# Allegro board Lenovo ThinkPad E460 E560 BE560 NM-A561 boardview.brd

Outline 251.2 x 195.15 mm; copper layers: TOP, GND1, IN1, IN2, VCC, IN3, GND2, BOTTOM. Coordinates in mm from the lower left corner of the outline.

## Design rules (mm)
net group 2: nets USB3P2_TXN_C USB3P2_TXP_C
net group AC: nets ACN ACP
net group CLKOUT_ITPXDP_: nets CLKOUT_ITPXDP_N CLKOUT_ITPXDP_P
net group CPU_EDP_AUX: nets CPU_EDP_AUX CPU_EDP_AUX#
net group CPU_EDP_TX0: nets CPU_EDP_TX0+ CPU_EDP_TX0-
net group CPU_EDP_TX1: nets CPU_EDP_TX1+ CPU_EDP_TX1-
net group CS1: nets CSN1 CSP1
net group DDI1_MUX_TX0: nets DDI1_MUX_TX0+_R DDI1_MUX_TX0-_R
net group DDI1_MUX_TX1: nets DDI1_MUX_TX1+_R DDI1_MUX_TX1-_R
net group DDI1_MUX_TX2: nets DDI1_MUX_TX2+_R DDI1_MUX_TX2-_R
net group DDI1_MUX_TX3: nets DDI1_MUX_TX3+_R DDI1_MUX_TX3-_R
net group DDRA_CTL: nets DDRA_CS0_DIMMA# DDRA_CS1_DIMMA#
net group DIFFPAIR0: nets CLK_PCIE_VGA CLK_PCIE_VGA#
net group DIFFPAIR15: nets USB20_N4_FFC_CON USB20_P4_FFC_CON
net group DIFFPAIR16: nets USB3P3_TXN_COAX_CON USB3P3_TXP_COAX_CON
net group DIFFPAIR23: nets USB3P2_TXN_CON USB3P2_TXP_CON
net group DIFFPAIR24: nets USB3P2_RXN_CON USB3P2_RXP_CON
net group DIFFPAIR30: nets USB3P4_RXN_COAX_CON USB3P4_RXP_COAX_CON
net group DIFFPAIR34: nets PCIE_CRX_C_GTX_N3 PCIE_CRX_C_GTX_P3
net group DIFFPAIR35: nets PCIE_CRX_C_GTX_N2 PCIE_CRX_C_GTX_P2
net group DIFFPAIR36: nets PCIE6_CRX_DTX_N PCIE6_CRX_DTX_P
net group DIFFPAIR37: nets USB3P5_TXN USB3P5_TXP
net group DIFFPAIR38: nets USB3P5_RXN USB3P5_RXP
net group DIFFPAIR39: nets USB3P5_RXN_CON USB3P5_RXP_CON
net group DIFFPAIR40: nets USB3P5_TXN_CON USB3P5_TXP_CON
net group DIFFPAIR41: nets USB3P5_TXN_C USB3P5_TXP_C
net group DIFFPAIR42: nets CPU_EDP_TX0+_CON CPU_EDP_TX0-_CON
net group DIFFPAIR43: nets CPU_EDP_TX1+_CON CPU_EDP_TX1-_CON
net group DIFFPAIR44: nets CPU_EDP_AUX#_CON CPU_EDP_AUX_CON
net group DIFFPAIR45: nets HDMI_TXC+_CON HDMI_TXC-_CON
net group DIFFPAIR46: nets DDI1_MUX_TX3+ DDI1_MUX_TX3-
net group DIFFPAIR47: nets DDI1_MUX_TX2+ DDI1_MUX_TX2-
net group DIFFPAIR48: nets DDI1_MUX_TX1+ DDI1_MUX_TX1-
net group DIFFPAIR49: nets DDI1_MUX_TX0+ DDI1_MUX_TX0-
net group DIFFPAIR50: nets PCH_MUX_AUX PCH_MUX_AUX#
net group DIFFPAIR51: nets USB20_N1_CON USB20_P1_CON
net group DIFFPAIR52: nets USB3P1_TXN_CON USB3P1_TXP_CON
net group DIFFPAIR53: nets USB3P1_TXN_C USB3P1_TXP_C
net group DIFFPAIR54: nets USB3P1_RXN_CON USB3P1_RXP_CON
net group DIFFPAIR55: nets PCIE4_CRX_DTX_N_C PCIE4_CRX_DTX_P_C
net group DIFFPAIR56: nets PCIE3_CTX_C_DRX_N PCIE3_CTX_C_DRX_P
net group DIFFPAIR58: nets USB20_N3_FFC_CON USB20_P3_FFC_CON
net group DIFFPAIR60: nets SATA_PTX_C_DRX_N0 SATA_PTX_C_DRX_P0
net group DIFFPAIR61: nets SATA_PRX_C_DTX_N0 SATA_PRX_C_DTX_P0
net group DIFFPAIR62: nets SATA_PTX_C_DRX_N1 SATA_PTX_C_DRX_P1
net group DOCK_TX0: nets DOCK_TX0+ DOCK_TX0-
net group DP: nets DOCK_AUX DOCK_AUX#
net group DP_H_HDMI_TX0: nets H_HDMI_TX0+ H_HDMI_TX0-
net group DP_H_HDMI_TX1: nets H_HDMI_TX1+ H_HDMI_TX1-
net group DP_H_HDMI_TX2: nets H_HDMI_TX2+ H_HDMI_TX2-
net group DP_N56767499: nets N56767499 N56767500
net group DP_PCIE6_CRX_DTX: nets PCIE6_CRX_C_DTX_N PCIE6_CRX_C_DTX_P
net group DP_PCIE6_CTX_DRX: nets PCIE6_CTX_DRX_N PCIE6_CTX_DRX_P
net group DP_PCIE_CRX_C_GTX_N0: nets PCIE_CRX_C_GTX_N0 PCIE_CRX_C_GTX_P0
net group DP_PCIE_CRX_C_GTX_N1: nets PCIE_CRX_C_GTX_N1 PCIE_CRX_C_GTX_P1
net group DP_PCIE_CRX_C_GTX_N3: nets PCIE_CRX_GTX_N3 PCIE_CRX_GTX_P3
net group DP_SATA_PRX_C_DTX_N1: nets SATA_PRX_C_DTX_N1 SATA_PRX_C_DTX_P1
net group FBA_CLK: nets FBB_WCKB0_1 FBB_WCKB0B_1
net group HDMI_TX0: nets HDMI_TX0+_CON HDMI_TX0-_CON
net group HDMI_TX1: nets HDMI_TX1+_CON HDMI_TX1-_CON
net group HDMI_TX2: nets HDMI_TX2+_CON HDMI_TX2-_CON
net group HDMI_TXC_CON: nets H_HDMI_TXC+ H_HDMI_TXC-
net group HGND: nets EXT_MIC_A EXT_MIC_B
net group MINIDP_TX1: nets DOCK_TX1+ DOCK_TX1-
net group PCH_MUX_AUX: nets PCH_MUX_AUX#_C PCH_MUX_AUX_C
net group PCIE3_CTX_C_DRX_: nets PCIE3_CTX_DRX_N PCIE3_CTX_DRX_P
net group PCIE4_CRX_DTX_: nets PCIE4_CRX_DTX_N PCIE4_CRX_DTX_P
net group PCIE4_CTX_C_DRX_: nets PCIE4_CTX_DRX_N PCIE4_CTX_DRX_P
net group PCIE6_CTX_DRX: nets PCIE6_CTX_C_DRX_N PCIE6_CTX_C_DRX_P
net group PCIE_CRX_C_GTX: nets PCIE_CRX_GTX_N1 PCIE_CRX_GTX_P1
net group PCIE_CRX_C_GTX_: nets PCIE_CRX_GTX_N0 PCIE_CRX_GTX_P0
net group PCIE_CRX_C_GTX_2: nets PCIE_CRX_GTX_N2 PCIE_CRX_GTX_P2
net group PCIE_WLAN_S20(15)/20(15): nets PCIE3_CRX_DTX_N PCIE3_CRX_DTX_P
net group PECI_18/18: nets H_PECI PECI
net group RTC_R: nets PCH_RTCRST# PCH_SRTCRST#
net group RTCX: nets PCH_RTCX1 PCH_RTCX2
net group SATA_PRX_C_DTX_P0: nets SATA_PRX_DTX_N0 SATA_PRX_DTX_P0
net group SATA_PRX_DTX_N1: nets SATA_PRX_DTX_N1 SATA_PRX_DTX_P1
net group SATA_PTX_C_DRX_N1: nets SATA_PTX_DRX_N1 SATA_PTX_DRX_P1
net group SATA_PTX_C_DRX_P0: nets SATA_PTX_DRX_N0 SATA_PTX_DRX_P0
net group SD_CLK_MS_DATA0: nets SD_CLK_MS_DATA0 SD_CLK_MS_DATA0_R
net group SD_CMD_MS_DATA2: nets SD_CMD_MS_DATA2 SD_CMD_MS_DATA2_R
net group SD_DATA0_MS_DATA1: nets SD_DATA0_MS_DATA1 SD_DATA0_MS_DATA1_R
net group SD_DATA2_MS_CLK: nets SD_DATA2_MS_CLK SD_DATA2_MS_CLK_R
net group SD_MS_DATA3: nets SD_MS_DATA3 SD_MS_DATA3_R
net group USB3P1: nets USB3P1_TXN USB3P1_TXP
net group USB3P1_RX: nets USB3P1_RXN USB3P1_RXP
net group USB3P2_RX: nets USB3P2_RXN USB3P2_RXP
net group USB20_P0: nets USB20_N1 USB20_P1
net group USB20_P1: nets USB20_N2_CON USB20_P2_CON
net group USB201: nets USB20N2 USB20P2
net group VSUM: nets VSUM+ VSUM-
net group 1: nets PCIE4_CTX_C_DRX_P
net group AUDIO_HP_S10: nets +MICBIASB HP_OUTL HP_OUTL_CON HP_OUTR HP_OUTR_CON N61210291
net group CPU SIDEBAND_S12(13.5): nets DDR3_DRAMRST# H_CPUPWRGD H_PROCHOT_EC H_THERMTRIP# THRMTRIP# VR_HOT#_R
net group DDI: nets AUXN AUXP DDI2_VGA_TX0+ DDI2_VGA_TX0- DDI2_VGA_TX1+ DDI2_VGA_TX1- ML0N ML0P ML1N ML1P PCH_VGA_AUX PCH_VGA_AUX#
net group DDR-DQS: nets DDR_A_DQS0 DDR_A_DQS3 DDR_A_DQS4 DDR_A_DQS5 DDR_A_DQS6 DDR_A_DQS7 DDR_A_DQS#0 DDR_A_DQS#3 DDR_A_DQS#4 DDR_A_DQS#5 DDR_A_DQS#6 DDR_A_DQS#7 DDR_B_DQS0 DDR_B_DQS1 DDR_B_DQS2 DDR_B_DQS3 DDR_B_DQS4 DDR_B_DQS5 DDR_B_DQS6 DDR_B_DQS7 DDR_B_DQS#0 DDR_B_DQS#1 DDR_B_DQS#2 DDR_B_DQS#3 DDR_B_DQS#4 DDR_B_DQS#5 DDR_B_DQS#6 DDR_B_DQS#7
net group DDRB_CTL: nets DDRB_CS0_DIMMB#
net group EDPCOMP_S25/25: nets EDP_COMP
net group FBB_CMD/CTL: nets FBA_RST#
net group HDA_S5/5: nets HDA_RST# HDA_SYNC PCH_HDA_RST# PCH_HDA_SDIN0 PCH_HDA_SDIN0_R PCH_HDA_SDOUT PCH_HDA_SYNC
net group LAN_S20/20: nets MDI_0+ MDI_0- MDI_1+ MDI_1- MDI_2+ MDI_2- MDI_3+ MDI_3- RJ45_TXD0N RJ45_TXD0P RJ45_TXD1N RJ45_TXD1P RJ45_TXD2N RJ45_TXD2P RJ45_TXD3N RJ45_TXD3P
net group LVDS: nets +LEDVDD
net group PCIE_CLK_S20(15)/20(15): nets CLK_PCIE_CR CLK_PCIE_CR# CLK_PCIE_LAN CLK_PCIE_LAN# CLK_PCIE_WLAN CLK_PCIE_WLAN#
net group PCIE_GPU: nets PCIE3_PTX_DRX_N2 PCIE3_PTX_DRX_P2 PCIE4_PTX_DRX_N3 PCIE4_PTX_DRX_P3 PCIE_CTX_C_GRX_N2 PCIE_CTX_C_GRX_N3 PCIE_CTX_C_GRX_P2 PCIE_CTX_C_GRX_P3
net group PCIE_LAN: nets PCIE1_PTX_DRX_N0 PCIE1_PTX_DRX_P0 PCIE2_PTX_DRX_N1 PCIE2_PTX_DRX_P1 PCIE4_CTX_C_DRX_N PCIE_CTX_C_GRX_N0 PCIE_CTX_C_GRX_N1 PCIE_CTX_C_GRX_P0 PCIE_CTX_C_GRX_P1
net group PWR: nets +1.65V_LDO +3V_LDO +3VALW_LAN APDIN P3 SPI_IO2 SPI_IO3 VSYSTEM
net group SMBUS_S7/7: nets EC_SMB_CK1 EC_SMB_DA1 PCH_SMB_CLK PCH_SMB_DATA PCH_SML0_CLK PCH_SML0_DAT PCH_SML1CLK PCH_SML1DATA PM_SMB_CLK PM_SMB_DAT
net group SPI: nets FSCE# LAN_WAKE# LAN_WAKE#_R PCH_SLP_LAN# PCH_SLP_WLAN# SPI_CS0#_8MB SPI_FMISO SPI_FMOSI# SPI_SI_8MB SPI_SO_8MB
net group SPI5/5: nets SPI_CS1#_4MB SPI_FSCK SPI_IO2_4MB SPI_IO2_8MB SPI_IO3_4MB SPI_IO3_8MB SPI_SI SPI_SI_4MB SPI_SO SPI_SO_4MB
net group SPI_CLK: nets CLK_PCI_EC DMIC_CLK HDA_BCLK N43769362 PCH_HDA_BCLK PCH_PCI_CLK_R SPI_CLK SPI_CLK_4MB SPI_CLK_8MB SPI_CLK_R
net group SVID_S18/18: nets VR_SVID_ALRT# VR_SVID_CLK VR_SVID_DAT
net group USB20: nets USB20_N2 USB20_N3 USB20_N4 USB20_N5 USB20_N5_CON USB20_N9 USB20_P2 USB20_P3 USB20_P4 USB20_P5 USB20_P5_CON USB20_P9
net group USB20_S20(15)/20(15): nets USB20_N6 USB20_N7 USB20_N7_CMOS USB20_P6 USB20_P7 USB20_P7_CMOS
net group USB30: nets USB3P2_TXN USB3P2_TXP USB3P3_RXN USB3P3_RXN_COAX_CON USB3P3_RXP USB3P3_RXP_COAX_CON USB3P3_TXN USB3P3_TXP USB3P4_RXN USB3P4_RXP USB3P4_TXN USB3P4_TXN_COAX_CON USB3P4_TXP USB3P4_TXP_COAX_CON
net group VGA: nets VGA_BLUE VGA_GREEN VGA_RED
net group WLAN_CTRL_S10/10: nets CL_CLK_WLAN CL_DATA_WLAN CL_RST_WLAN#
nets with their own width: min track width 0.254; nets +3VALW

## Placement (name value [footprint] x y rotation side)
AOU1  -  [TPS2546RTER_QFN16_4X4]  35.95 17.85 90 top
C1  0.1U_0402_10V6-K  [C_0402]  119.44 179.29 270 bottom
C2  2200P_0402_50V7-K  [C_0402]  118.17 177.76 180 bottom
C3  2200P_0402_50V7-K  [C_0402]  116.41 177.76 180 bottom
C4  100P_0402_50V8-J  [C_0402]  34.75 105.04 90 bottom
C5  100P_0402_50V8-J  [C_0402]  50.48 41.67 0 bottom
C8  1U_0402_6.3VA-K  [C_0402]  86.86 134.45 315 bottom
C9  4.7U_0603_6.3V6-K  [C_0603]  92.55 135.85 135 bottom
C10  1U_0402_6.3VA-K  [C_0402]  94.92 143.81 225 bottom
C11  4.7U_0603_6.3V6-K  [C_0603]  93.57 138.73 225 bottom
C12  4.7U_0805_25V6-K  [C_0805]  100.52 134.45 315 top
C13  0.1U_0402_10V7-K  [C_0402]  94.87 127.5 135 top
C14  0.1U_0402_10V7-K  [C_0402]  94.23 126.87 135 top
C15  0.1U_0402_10V7-K  [C_0402]  93.6 126.23 135 top
C16  0.1U_0402_10V7-K  [C_0402]  92.96 125.6 135 top
C17  0.1U_0402_10V7-K  [C_0402]  96.14 128.77 135 top
C18  0.1U_0402_10V7-K  [C_0402]  95.5 128.14 135 top
C19  10U_0805_10V6-K  [C_0805]  196.91 128.47 90 bottom
C20  10U_0805_10V6-K  [C_0805]  198.68 128.47 90 bottom
C21  1U_0402_10V6-K  [C_0402]  195.51 128.56 90 bottom
C22  0.1U_0402_25V6-K  [C_0402]  193.73 128.56 90 bottom
C23  1000P_0402_50V7-K  [C_0402]  194.62 128.56 90 bottom
C24  .01U_0402_16V7-K  [C_0402]  172.9 128.89 270 bottom
C25  .01U_0402_16V7-K  [C_0402]  173.79 128.89 270 bottom
C26  .01U_0402_16V7-K  [C_0402]  176.71 128.89 270 bottom
C27  .01U_0402_16V7-K  [C_0402]  177.6 128.89 270 bottom
C28  0.1U_0402_10V7-K  [C_0402]  87.86 121.72 90 top
C29  0.1U_0402_10V7-K  [C_0402]  86.96 121.72 90 top
C44  100P_0402_50V8J  [C_0402]  31.8 100.42 180 top
C45  100P_0402_50V8J  [C_0402]  31.8 101.31 180 top
C50  0.1U_0402_10V6-K  [C_0402]  120.94 123.94 0 bottom
C51  10U_0603_6.3V6-M  [C_0603]  120.92 122.87 0 bottom
C52  0.1U_0402_10V6-K  [C_0402]  215.91 93.64 180 top
C69  1U_0402_6.3VA-K  [C_0402]  183.65 25.82 180 top
C70  0.1U_0402_10V7-K  [C_0402]  191.37 28.26 270 top
C71  1000P_0402_25V7-K  [C_0402]  188.96 25.03 0 top
C72  100P_0402_50V8-J  [C_0402]  188.96 24.14 0 top
C73  1U_0402_6.3VA-K  [C_0402]  183.24 23.36 180 top
C74  0.1U_0402_10V7-K  [C_0402]  190 22.26 90 top
C75  .01U_0402_16V7-K  [C_0402]  214.79 37.15 90 top
C115  0.1U_0402_10V6-K  [C_0402]  235.82 144.34 180 top
C116  0.1U_0402_10V6-K  [C_0402]  235.82 143.45 180 top
C119  0.1U_0402_10V6-K  [C_0402]  30.33 23.48 270 top
C121  0.1U_0402_10V7-K  [C_0402]  24.01 44.11 180 top
C122  150U_B2_6.3VM_R35M  [C_B2]  19.97 48.58 270 bottom
C123  470P_0402_50V7-K  [C_0402]  17.53 49.26 90 bottom
C124  0.1U_0402_10V7-K  [C_0402]  24.01 43.22 180 top
C129  .01U_0402_16V7-K  [C_0402]  222.87 42.84 0 bottom
C130  .01U_0402_16V7-K  [C_0402]  222.87 43.73 0 bottom
C131  4.7U_0603_6.3V6-K  [C_0603]  223.96 46.46 270 bottom
C132  1U_0402_6.3VA-K  [C_0402]  222 50.84 180 bottom
C164  .01U_0402_16V7-K  [C_0402]  222.87 40.93 0 bottom
C165  .01U_0402_16V7-K  [C_0402]  222.87 41.82 0 bottom
C171  .01U_0402_16V7-K  [C_0402]  242.58 182.28 180 top
C172  1U_0402_6.3VA-K  [C_0402]  243.92 182.28 90 top
C202  2200P_0402_50V7-K  [C_0402]  192.84 128.56 90 bottom
C203  47P_0402_50V8-J  [C_0402]  191.95 128.56 90 bottom
C204  2200P_0402_50V7-K  [C_0402]  185.65 123.36 0 top
C205  47P_0402_50V8-J  [C_0402]  185.68 124.35 0 top
C747  2200P_0402_25V7-K  [C_0402]  130.44 64.17 180 top
C749  10U_0402_6.3V  [C_0402]  127.31 68.9 270 top
C750  1U_0402_6.3V6-K  [C_0402]  185.35 14.47 270 top
C751  4.7U_0603_10V6-K  [C_0603]  189.86 15.53 0 top
C8496  0.1U_0402_10V6-K  [C_0402]  114.13 116.04 270 bottom
C8497  0.1U_0402_10V6-K  [C_0402]  115.02 116.04 270 bottom
C8498  0.1U_0402_10V6-K  [C_0402]  123.6 126.89 270 bottom
C8499  10U_0603_6.3V6-M  [C_0603]  112.54 123.1 180 bottom
C8528  470P_0402_50V7-K  [C_0402]  33.92 9.9 0 top
C8529  0.1U_0402_10V7-K  [C_0402]  26.47 16.93 180 top
C8530  0.1U_0402_10V7-K  [C_0402]  26.47 15.97 180 top
C8531  150U_B2_6.3VM_R35M  [C_B2]  33.45 12.05 180 top
C8532  0.1U_0402_10V7-K  [C_0402]  39.1 17.31 0 top
C8533  2200P_0402_50V7-K  [C_0402]  101.66 139.99 225 top
C8534  2200P_0402_50V7-K  [C_0402]  94.04 135.85 315 bottom
C8536  4.7U_0603_6.3V6-K  [C_0603]  63.61 57.49 180 top
C8537  0.1U_0402_10V7-K  [C_0402]  63.4 58.69 180 top
C8540  0.22U_0402_10V6-K  [C_0402]  69.53 53.96 270 top
C8541  0.1U_0402_6.3V7-K  [C_0402]  130.54 67.98 90 top
C8542  0.1U_0402_10V6-K  [C_0402]  102.41 82.91 0 top
C8543  10U_0402_6.3V6-M  [C_0402]  126.88 63.86 180 top
C8544  0.1U_0402_10V7-K  [C_0402]  124.33 65.11 90 top
C8545  0.1U_0402_10V6-K  [C_0402]  23.17 23.99 270 top
CA1  0.1U_0402_10V7-K  [C_0402]  195.15 26.38 270 top
CA2  4.7U_0603_10V6-K  [C_0603]  196.97 21.5 0 top
CA3  4.7U_0603_10V6-K  [C_0603]  196.97 20.28 0 top
CA4  0.1U_0402_10V7-K  [C_0402]  203.46 20.28 180 top
CA5  0.1U_0402_10V7-K  [C_0402]  203.89 23.74 180 top
CA6  0.1U_0402_10V7-K  [C_0402]  214.08 27.6 270 top
CA7  4.7U_0603_10V6-K  [C_0603]  212.99 26.11 90 top
CA8  0.1U_0402_10V7-K  [C_0402]  213.62 16.55 0 top
CA9  1U_0402_6.3VA-K  [C_0402]  213.62 15.64 0 top
CA10  0.1U_0402_10V7-K  [C_0402]  210.67 15.1 270 top
CA11  2.2U_0402_6.3V6-M  [C_0402]  211.74 15.04 270 top
CA12  0.1U_0402_10V7-K  [C_0402]  195.18 27.22 90 top
CA13  1U_0402_6.3VA-K  [C_0402]  208.49 14.92 270 top
CA14  1U_0402_6.3VA-K  [C_0402]  203.82 18.05 180 top
CA15  1U_0402_6.3VA-K  [C_0402]  213.39 13.86 270 top
CA16  0.1U_0402_10V7-K  [C_0402]  203.05 25.95 0 top
CA17  1U_0402_6.3V6-K  [C_0402]  205.11 17.16 180 top
CA18  2.2U_0402_6.3V6-M  [C_0402]  205.81 16.07 180 top
CA19  0.1U_0402_10V7-K  [C_0402]  209.38 13.98 90 top
CA22  0.1U_0402_10V7-K  [C_0402]  198.35 29.12 0 top
CA23  0.1U_0402_10V7-K  [C_0402]  201.94 27.29 90 top
CA24  0.1U_0402_10V7-K  [C_0402]  201.99 29.1 0 top
CA25  470P_0402_50V7-K  [C_0402]  201.05 23.53 180 top
CA26  470P_0402_50V7-K  [C_0402]  201.05 25.82 180 top
CA27  470P_0402_50V7-K  [C_0402]  201.05 19.98 180 top
CA28  470P_0402_50V7-K  [C_0402]  201.05 17.69 180 top
CA29  2.2U_0402_6.3V6-K  [C_0402]  215.6 17.54 0 top
CA30  2.2U_0402_6.3V6-K  [C_0402]  215.6 18.43 0 top
CA31  10U_0603_6.3V6-M  [C_0603]  215.66 19.47 0 top
CA32  10U_0603_6.3V6-M  [C_0603]  215.69 20.66 0 top
CA40  150P_0402_50V8-J  [C_0402]  215.98 24.96 270 top
CA42  4.7U_0603_10V6-K  [C_0603]  208.79 26.09 90 top
CA43  47P_0402_50V8-J  [C_0402]  215.88 26.68 90 top
CC1  1U_0402_10V6K  [C_0402]  118.4 72.76 180 top
CC2  1U_0402_10V6-K  [C_0402]  102.41 81.13 0 top
CC3  3.9P_0402_50V8-B  [C_0402]  116.31 88.89 90 top
CC4  3.9P_0402_50V8-B  [C_0402]  116.31 88.03 270 top
CC5  1U_0402_10V6K  [C_0402]  115.7 72.73 0 top
CC6  12P_0402_50V8-J  [C_0402]  90.53 118.21 0 bottom
CC7  12P_0402_50V8-J  [C_0402]  89.67 118.21 180 bottom
CC9  100P_0402_25V8J  [C_0402]  45.95 108.14 180 top
CC18  0.1U_0402_10V7-K  [C_0402]  100.41 110.71 270 bottom
CC19  0.1U_0402_10V7-K  [C_0402]  101.3 110.71 270 bottom
CC20  0.1U_0402_10V7-K  [C_0402]  101.15 118.48 270 bottom
CC21  0.1U_0402_10V7-K  [C_0402]  100.26 118.48 270 bottom
CC22  0.1U_0402_10V6-K  [C_0402]  79.38 132.25 180 bottom
CC23  0.1U_0402_10V7-K  [C_0402]  94.54 118.48 270 bottom
CC24  0.1U_0402_10V7-K  [C_0402]  94.42 115.48 270 bottom
CC25  0.1U_0402_10V7-K  [C_0402]  138.13 124.98 270 bottom
CC26  0.1U_0402_10V7-K  [C_0402]  227.74 15.46 180 top
CC46  1U_0402_10V6K  [C_0402]  126.87 97.46 270 bottom
CC47  1U_0402_10V6K  [C_0402]  98 93.18 180 top
CC49  1U_0402_10V6K  [C_0402]  100.01 99.81 0 top
CC50  1U_0402_10V6K  [C_0402]  102.14 96.41 180 top
CC52  1U_0402_10V6K  [C_0402]  99.35 96.69 180 top
CC58  1U_0402_10V6K  [C_0402]  100.96 84.38 270 top
CC59  1U_0402_10V6K  [C_0402]  102.41 82.02 0 top
CC60  1U_0402_10V6K  [C_0402]  120.12 88.24 0 top
CC61  1U_0402_10V6K  [C_0402]  125.02 88.89 0 top
CC68  1U_0402_10V6K  [C_0402]  97.8 104.74 180 top
CC69  1U_0402_10V6K  [C_0402]  97.67 107.61 180 top
CC70  1U_0402_10V6K  [C_0402]  95.26 104.71 90 top
CC86  0.1U_0402_10V7-K  [C_0402]  96.32 118.48 270 bottom
CC87  0.1U_0402_10V7-K  [C_0402]  97.21 118.48 270 bottom
CC88  0.1U_0402_10V7-K  [C_0402]  99.24 118.48 270 bottom
CC89  0.1U_0402_10V7-K  [C_0402]  98.23 118.48 270 bottom
CC90  0.1U_0402_10V7-K  [C_0402]  95.43 118.48 270 bottom
CC91  0.1U_0402_10V7-K  [C_0402]  95.31 115.48 270 bottom
CC92  0.1U_0402_10V7-K  [C_0402]  102.16 118.48 270 bottom
CC93  0.1U_0402_10V7-K  [C_0402]  103.05 118.48 270 bottom
CC94  1U_0402_10V6K  [C_0402]  85.53 84.83 270 top
CC95  1U_0402_10V6K  [C_0402]  98.61 94.07 0 top
CC96  1U_0402_10V6K  [C_0402]  101.97 91.56 270 top
CC97  1U_0402_10V6K  [C_0402]  115.63 94.68 0 top
CC99  1U_0402_10V6K  [C_0402]  98.18 72.05 180 top
CC102  100P_0402_25V8J  [C_0402]  45.95 109.03 180 top
CC104  10U_0603_6.3V6-M  [C_0603]  85.11 89.1 180 top
CC105  10U_0603_6.3V6-M  [C_0603]  93.26 89.24 180 top
CC106  1U_0201_6.3V6-M  [C_0201]  87.01 87.67 0 top
CC107  1U_0201_6.3V6-M  [C_0201]  86.29 88.94 0 top
CC108  1U_0201_6.3V6-M  [C_0201]  86.72 89.68 90 top
CC109  1U_0201_6.3V6-M  [C_0201]  86.09 89.68 90 top
CC123  10U_0603_6.3V6-M  [C_0603]  81.81 94.48 180 top
CC129  10U_0603_6.3V6-M  [C_0603]  76.17 90.67 180 top
CC130  10U_0603_6.3V6-M  [C_0603]  76.17 91.96 180 top
CC131  10U_0603_6.3V6-M  [C_0603]  77.54 91.91 0 top
CC133  10U_0603_6.3V6-M  [C_0603]  71.1 93.04 270 top
CC136  10U_0603_6.3V6-M  [C_0603]  88.26 114.59 90 bottom
CC137  10U_0603_6.3V6-M  [C_0603]  89.53 89.24 0 top
CC138  10U_0603_6.3V6-M  [C_0603]  95.05 117.07 90 top
CC139  10U_0603_6.3V6-M  [C_0603]  84.88 100.37 180 top
CC140  10U_0603_6.3V6-M  [C_0603]  86.99 115.17 90 top
CC141  10U_0603_6.3V6-M  [C_0603]  86.99 114.59 90 bottom
CC142  1U_0201_6.3V6-M  [C_0201]  88.28 91.61 0 top
CC143  1U_0201_6.3V6-M  [C_0201]  84.89 91.56 0 top
CC144  1U_0201_6.3V6-M  [C_0201]  116.26 111.63 90 top
CC145  1U_0201_6.3V6-M  [C_0201]  83.69 91.1 180 top
CC146  1U_0201_6.3V6-M  [C_0201]  78.2 95.57 0 top
CC147  1U_0201_6.3V6-M  [C_0201]  78.02 91.02 0 top
CC148  1U_0201_6.3V6-M  [C_0201]  72.3 97.84 270 top
CC149  1U_0201_6.3V6-M  [C_0201]  73.92 96.92 90 top
CC150  1U_0201_6.3V6-M  [C_0201]  78.17 98.57 0 top
CC151  1U_0201_6.3V6-M  [C_0201]  78.15 96.18 0 top
CC152  1U_0201_6.3V6-M  [C_0201]  54.79 92.71 90 top
CC153  1U_0201_6.3V6-M  [C_0201]  72.61 94.5 270 top
CC154  1U_0201_6.3V6-M  [C_0201]  53.78 96.09 270 top
CC155  1U_0201_6.3V6-M  [C_0201]  73.36 92.76 270 top
CC156  1U_0201_6.3V6-M  [C_0201]  53.78 98.81 90 top
CC157  1U_0201_6.3V6-M  [C_0201]  72.63 95.88 270 top
CC158  1U_0201_6.3V6-M  [C_0201]  72 94.5 270 top
CC159  1U_0201_6.3V6-M  [C_0201]  73.84 94.4 270 top
CC160  1U_0201_6.3V6-M  [C_0201]  78.17 97.96 0 top
CC161  1U_0201_6.3V6-M  [C_0201]  78.02 90.44 0 top
CC170  1U_0201_6.3V6-M  [C_0201]  81.36 91.07 180 top
CC171  1U_0201_6.3V6-M  [C_0201]  82.18 89.79 270 top
CC172  1U_0201_6.3V6-M  [C_0201]  90.6 91.61 180 top
CC173  1U_0201_6.3V6-M  [C_0201]  87 105.18 270 top
CC174  1U_0201_6.3V6-M  [C_0201]  87.95 100.62 180 top
CC175  1U_0201_6.3V6-M  [C_0201]  87.17 91.49 180 top
CC176  1U_0201_6.3V6-M  [C_0201]  84.89 91 0 top
CC177  1U_0201_6.3V6-M  [C_0201]  90.6 92.24 180 top
CC178  1U_0201_6.3V6-M  [C_0201]  88.28 92.88 0 top
CC179  1U_0201_6.3V6-M  [C_0201]  90.21 100.67 0 top
CC190  1U_0201_6.3V6-M  [C_0201]  86.4 104 0 top
CC191  1U_0201_6.3V6-M  [C_0201]  89.55 98.46 0 top
CC192  1U_0201_6.3V6-M  [C_0201]  88.88 98.46 180 top
CC193  1U_0201_6.3V6-M  [C_0201]  91.87 100.67 0 top
CC194  1U_0201_6.3V6-M  [C_0201]  81.36 90.49 180 top
CC195  1U_0201_6.3V6-M  [C_0201]  87.18 90.9 180 top
CC196  1U_0201_6.3V6-M  [C_0201]  90.58 92.88 180 top
CC197  1U_0201_6.3V6-M  [C_0201]  91.98 102.36 90 top
CC198  1U_0201_6.3V6-M  [C_0201]  84.87 90.41 0 top
CC199  1U_0201_6.3V6-M  [C_0201]  83.69 91.66 180 top
CC200  1U_0201_6.3V6-M  [C_0201]  85.24 104.03 180 top
CC201  1U_0201_6.3V6-M  [C_0201]  116.9 111.63 90 top
CC202  1U_0201_6.3V6-M  [C_0201]  81.57 89.79 270 top
CC203  1U_0201_6.3V6-M  [C_0201]  91.87 100.12 0 top
CC204  1U_0201_6.3V6-M  [C_0201]  83.69 90.54 180 top
CC205  1U_0201_6.3V6-M  [C_0201]  91.98 104.62 270 top
CC206  1U_0201_6.3V6-M  [C_0201]  88.29 92.25 0 top
CC207  1U_0201_6.3V6-M  [C_0201]  91.71 92.06 0 top
CC208  1U_0201_6.3V6-M  [C_0201]  90.1 105.63 90 top
CC209  1U_0201_6.3V6-M  [C_0201]  83.94 89.98 180 top
CC218  10U_0603_6.3V6-M  [C_0603]  83.27 104.6 270 top
CC221  10U_0603_6.3V6-M  [C_0603]  88.26 115.17 90 top
CC222  10U_0603_6.3V6-M  [C_0603]  81.81 96.97 180 top
CC223  10U_0603_6.3V6-M  [C_0603]  81.81 98.24 180 top
CC224  10U_0603_6.3V6-M  [C_0603]  90.8 90.69 0 top
CC225  10U_0603_6.3V6-M  [C_0603]  81.81 95.72 180 top
CC226  10U_0603_6.3V6-M  [C_0603]  92.94 83.95 270 top
CC227  10U_0603_6.3V6-M  [C_0603]  90.96 81.97 90 top
CC228  10U_0603_6.3V6-M  [C_0603]  86.95 81.71 90 top
CC229  10U_0603_6.3V6-M  [C_0603]  89.77 81.97 90 top
CC230  10U_0603_6.3V6-M  [C_0603]  81.18 82.48 90 top
CC231  1U_0201_6.3V6-M  [C_0201]  82.07 82.68 90 top
CC232  10U_0603_6.3V6-M  [C_0603]  82.96 82.5 90 top
CC233  1U_0201_6.3V6-M  [C_0201]  96.49 81.07 180 top
CC234  1U_0201_6.3V6-M  [C_0201]  89.21 85.23 270 top
CC235  1U_0201_6.3V6-M  [C_0201]  94.9 83.54 180 top
CC236  10U_0603_6.3V6-M  [C_0603]  94.71 93.56 0 top
CC237  10U_0603_6.3V6-M  [C_0603]  95.17 103.27 180 top
CC239  10U_0603_6.3V6-M  [C_0603]  94.58 98.24 0 top
CC241  10U_0603_6.3V6-M  [C_0603]  95.32 100.37 0 top
CC244  10U_0603_6.3V6-M  [C_0603]  96.21 103.54 0 top
CC245  10U_0603_6.3V6-M  [C_0603]  95.01 94.78 0 top
CC247  10U_0603_6.3V6-M  [C_0603]  95.83 91.6 0 top
CC249  1U_0201_6.3V6-M  [C_0201]  95.95 90.46 0 top
CC250  1U_0201_6.3V6-M  [C_0201]  94.18 92.17 180 top
CC251  1U_0201_6.3V6-M  [C_0201]  95.78 92.52 0 top
CC252  1U_0201_6.3V6-M  [C_0201]  95.5 95.67 0 top
CC253  1U_0201_6.3V6-M  [C_0201]  95.5 96.23 0 top
CC254  1U_0201_6.3V6-M  [C_0201]  95.5 96.79 0 top
CC255  1U_0201_6.3V6-M  [C_0201]  95.5 97.35 0 top
CC256  1U_0402_10V6K  [C_0402]  88.53 89.22 180 top
CC257  1U_0402_10V6K  [C_0402]  96.22 89.02 0 top
CC258  47U_0805_6.3V6-M  [C_0805]  118.75 98.67 270 bottom
CC259  0.1U_0402_10V6-K  [C_0402]  106.04 82.13 90 top
CC260  0.1U_0402_10V6-K  [C_0402]  102.61 84.7 270 top
CC261  0.1U_0402_10V6-K  [C_0402]  105.15 84.32 270 top
CC262  1U_0402_10V6K  [C_0402]  100.56 95.04 0 top
CC263  1U_0402_10V6K  [C_0402]  100.31 93.26 0 top
CC264  1U_0402_10V6K  [C_0402]  102.06 93.26 0 top
CC271  47U_0805_6.3V6-M  [C_0805]  122.29 91.96 90 top
CC272  47U_0805_6.3V6-M  [C_0805]  122.36 93.66 270 bottom
CC273  0.1U_0402_10V6-K  [C_0402]  103.49 94.34 0 top
CC274  0.1U_0402_10V6-K  [C_0402]  98.35 84.1 90 top
CD1  2.2U_0402_6.3V6-K  [C_0402]  61.64 37.6 270 top
CD2  0.022U_0402_25V7-K  [C_0402]  57.97 39.49 270 top
CD3  0.1U_0402_10V7-K  [C_0402]  60.75 37.6 270 top
CD8  1U_0402_6.3VA-K  [C_0402]  93.77 29.35 270 top
CD9  1U_0402_6.3VA-K  [C_0402]  97.46 29.35 270 top
CD10  1U_0402_6.3VA-K  [C_0402]  84.88 28.18 90 top
CD11  1U_0402_6.3VA-K  [C_0402]  86.24 36.57 90 top
CD12  0.022U_0402_25V7-K  [C_0402]  104.2 24.73 90 top
CD13  10U_0603_6.3V6-M  [C_0603]  93.65 37.84 270 top
CD14  10U_0603_6.3V6-M  [C_0603]  97.08 37.84 270 top
CD15  10U_0603_6.3V6-M  [C_0603]  89.74 36.43 90 top
CD16  10U_0603_6.3V6-M  [C_0603]  92.25 29.46 270 top
CD17  0.1U_0402_10V7-K  [C_0402]  99.75 25.64 270 top
CD18  2.2U_0402_6.3V6-K  [C_0402]  100.64 25.64 270 top
CD19  10U_0603_6.3V6-M  [C_0603]  99.93 37.85 270 top
CD20  10U_0603_6.3V6-M  [C_0603]  99.24 29.59 270 top
CD21  10U_0603_6.3V6-M  [C_0603]  87.56 29.57 270 top
CD22  330U_D2_2V_Y  [C_D2]  70.01 22.52 90 top
CD23  1U_0402_6.3VA-K  [C_0402]  124.43 37.78 0 top
CD24  1U_0402_6.3VA-K  [C_0402]  124.43 27.62 0 top
CD25  1U_0402_6.3VA-K  [C_0402]  124.43 28.64 0 top
CD26  1U_0402_6.3VA-K  [C_0402]  124.43 29.65 0 top
CD29  2.2U_0402_6.3V6-K  [C_0402]  120.2 36.43 90 top
CD30  0.1U_0402_10V6-K  [C_0402]  121.34 36.41 90 top
CD31  0.022U_0402_25V7-K  [C_0402]  57.38 52.67 270 top
CD32  0.1U_0402_10V7-K  [C_0402]  60.05 50.87 270 top
CD33  2.2U_0402_6.3V6-K  [C_0402]  60.92 50.87 270 top
CD38  1U_0402_6.3VA-K  [C_0402]  92.06 49.7 90 top
CD39  1U_0402_6.3VA-K  [C_0402]  87.61 43.6 90 top
CD40  1U_0402_6.3VA-K  [C_0402]  90.1 49.7 90 top
CD41  1U_0402_6.3VA-K  [C_0402]  93.5 49.67 90 top
CD42  10U_0603_6.3V6-M  [C_0603]  96.09 50.8 270 top
CD43  10U_0603_6.3V6-M  [C_0603]  92 42.92 270 top
CD44  10U_0603_6.3V6-M  [C_0603]  86.99 51.09 180 top
CD45  10U_0603_6.3V6-M  [C_0603]  83.28 49.42 180 top
CD46  10U_0603_6.3V6-M  [C_0603]  84.12 42.48 180 top
CD47  10U_0603_6.3V6-M  [C_0603]  96.51 41.19 0 top
CD48  10U_0603_6.3V6-M  [C_0603]  94.8 50.8 270 top
CD49  0.1U_0402_10V7-K  [C_0402]  100.39 42.79 270 top
CD51  1U_0402_6.3VA-K  [C_0402]  124.95 41.44 0 top
CD52  1U_0402_6.3VA-K  [C_0402]  124.95 43.47 0 top
CD53  1U_0402_6.3VA-K  [C_0402]  124.95 40.55 0 top
CD54  1U_0402_6.3VA-K  [C_0402]  124.95 42.58 0 top
CD55  10U_0603_6.3V6-M  [C_0603]  124.58 39.28 0 top
CD56  10U_0603_6.3V6-M  [C_0603]  124.96 44.62 0 top
CD57  2.2U_0402_6.3V6-K  [C_0402]  122.82 45.76 180 top
CD58  0.1U_0402_10V6-K  [C_0402]  122.82 44.87 180 top
CD59  0.1U_0402_10V7-K  [C_0402]  66.22 25.95 0 top
CD60  0.1U_0402_10V7-K  [C_0402]  68.41 43.65 270 top
CE1  47P_0402_50V8-J  [C_0402]  198.81 39.74 270 top
CE2  0.1U_0402_25V6-K  [C_0402]  182.36 53.79 270 top
CE3  1000P_0402_50V7-K  [C_0402]  183.25 53.79 270 top
CE4  0.1U_0402_25V6-K  [C_0402]  183.2 45.58 180 top
CE5  0.1U_0402_25V6-K  [C_0402]  200.72 39.74 270 top
CE6  0.1U_0402_25V6-K  [C_0402]  204 54.47 0 top
CE7  0.1U_0402_25V6-K  [C_0402]  204.92 48.63 180 top
CE8  0.1U_0402_25V6-K  [C_0402]  192.9 61 90 top
CE9  0.1U_0402_25V6-K  [C_0402]  192.28 39.87 270 top
CE10  0.1U_0402_25V6-K  [C_0402]  201.61 39.74 270 top
CE11  1U_0402_10V6-K  [C_0402]  208.72 50.51 90 top
CE12  100P_0402_50V8-J  [C_0402]  192.1 37.52 270 top
CE13  220P_0402_50V7-K  [C_0402]  204.92 52.82 180 top
CE14  0.1U_0402_25V6-K  [C_0402]  210 58.46 180 top
CE15  10P_0402_50V8-J  [C_0402]  206.7 49.52 180 top
CE16  100P_0402_50V8-J  [C_0402]  183.2 57.39 180 top
CE17  47P_0402_50V8-J  [C_0402]  184.08 38.83 90 top
CG1  0.1U_0402_10V6-K  [C_0402]  195.99 67.22 90 top
CG2  .01U_0402_16V7-K  [C_0402]  199.09 70.09 180 top
CG3  10U_0603_6.3V6-M  [C_0603]  200.21 70.52 0 top
CG4  .01U_0402_16V7-K  [C_0402]  196.35 70.04 90 top
CG5  1U_0402_10V6K  [C_0402]  201.45 64.43 270 top
CG6  10U_0603_6.3V6-M  [C_0603]  208.77 66.97 0 top
CL1  0.1U_0402_10V7-K  [C_0402]  53.91 113.34 180 top
CL2  0.1U_0402_10V7-K  [C_0402]  53.91 114.23 180 top
CL3  1U_0402_6.3VA-K  [C_0402]  49.59 123.33 90 top
CL4  0.1U_0402_10V7-K  [C_0402]  48.57 126.1 270 top
CL5  0.1U_0402_10V7-K  [C_0402]  49.59 126.1 270 top
CL6  22U_0805_6.3V6-M  [C_0805]  52.6 126.63 180 bottom
CL7  15P_0402_50V8-J  [C_0402]  45.45 122.72 0 top
CL8  15P_0402_50V8-J  [C_0402]  44.58 122.72 180 top
CL9  0.1U_0402_25V6-K  [C_0402]  37.59 112.32 270 top
CL10  1000P_1808_3KV7k~D  [C_1808]  23.31 117.51 180 bottom
CL11  0.1U_0402_10V6-K  [C_0402]  19.11 107.89 270 bottom
CL12  .01U_0402_16V7-K  [C_0402]  18.04 108.18 270 bottom
CL13  1U_0402_10V6K  [C_0402]  36.7 112.32 270 top
CL17  .01U_0402_16V7-K  [C_0402]  59.67 119.34 180 top
CRF1  2200P_0402_50V7-K  [C_0402]  95.71 29.38 270 top
CRF2  47P_0402_50V8-J  [C_0402]  94.82 29.38 270 top
CRF3  2200P_0402_50V7-K  [C_0402]  103.18 22.34 90 top
CRF4  47P_0402_50V8-J  [C_0402]  104.04 22.34 90 top
CRF5  2200P_0402_50V7-K  [C_0402]  225.05 51.35 180 bottom
CRF6  47P_0402_50V8-J  [C_0402]  225.05 50.46 180 bottom
CRF7  2200P_0402_50V7-K  [C_0402]  92.77 134.63 315 bottom
CRF8  47P_0402_50V8-J  [C_0402]  93.4 135.24 315 bottom
CRF9  2200P_0402_50V7-K  [C_0402]  95.15 137.04 315 bottom
CRF10  47P_0402_50V8-J  [C_0402]  96.55 138.39 45 bottom
CRF11  2200P_0402_50V7-K  [C_0402]  101.02 138.22 0 top
CRF12  47P_0402_50V8-J  [C_0402]  101.02 137.33 0 top
CRF13  2200P_0402_50V7-K  [C_0402]  96.4 133.55 135 bottom
CRF14  47P_0402_50V8-J  [C_0402]  95.75 132.9 135 bottom
CRF15  2200P_0402_50V7-K  [C_0402]  56.6 122.39 90 bottom
CRF16  47P_0402_50V8-J  [C_0402]  55.73 122.39 90 bottom
CRF17  2200P_0402_50V7-K  [C_0402]  59.52 119.85 180 bottom
CRF18  47P_0402_50V8-J  [C_0402]  59.52 118.86 180 bottom
CRF21  2200P_0402_50V7-K  [C_0402]  248.72 160.44 270 bottom
CRF22  47P_0402_50V8-J  [C_0402]  249.61 160.44 270 bottom
CT24  3P_0402_50V8-C  [C_0402]  15.55 83.91 90 top
CT25  3P_0402_50V8-C  [C_0402]  13.52 80.25 270 top
CT26  3P_0402_50V8-C  [C_0402]  15.55 81.62 90 top
CT27  3P_0402_50V8-C  [C_0402]  13.52 82.54 270 top
CT28  3P_0402_50V8-C  [C_0402]  13.52 84.83 270 top
CT29  3P_0402_50V8-C  [C_0402]  15.55 79.34 90 top
CT31  0.1U_0402_10V6-K  [C_0402]  17.76 90.84 0 top
CV1  0.1U_0402_10V7-K  [C_0402]  136.68 131.33 270 top
CV2  0.1U_0402_10V7-K  [C_0402]  137.57 131.33 270 top
CV3  0.1U_0402_10V7-K  [C_0402]  135.67 131.33 270 top
CV4  0.1U_0402_10V7-K  [C_0402]  134.78 131.33 270 top
CV5  0.1U_0402_10V7-K  [C_0402]  133.76 131.33 270 top
CV6  0.1U_0402_10V7-K  [C_0402]  132.87 131.33 270 top
CV7  0.1U_0402_10V7-K  [C_0402]  131.6 131.33 270 top
CV8  0.1U_0402_10V7-K  [C_0402]  130.71 131.33 270 top
CV17  22P_0402_50V8-J  [C_0402]  166.6 130.85 0 bottom
CV18  22P_0402_50V8-J  [C_0402]  164.47 130.21 180 bottom
CV19  0.1U_0402_10V7-K  [C_0402]  153.83 117.36 180 top
CV20  0.1U_0402_10V7-K  [C_0402]  155.53 116.35 0 top
CV21  10U_0603_6.3V6-M  [C_0603]  149.04 140.43 180 top
CV22  .01U_0402_16V7-K  [C_0402]  149.1 155.31 180 top
CV23  2.2U_0402_6.3V6-K  [C_0402]  115.73 140.91 90 top
CV24  1U_0402_10V6-K  [C_0402]  148.11 143.19 90 top
CV25  1U_0402_10V6-K  [C_0402]  146.31 140.2 90 top
CV26  0.1U_0402_10V7-K  [C_0402]  137.72 150.79 270 top
CV27  2.2U_0402_6.3V6-K  [C_0402]  145.57 154.12 0 top
CV28  2.2U_0402_6.3V6-K  [C_0402]  136.3 152.49 270 top
CV29  2.2U_0402_6.3V6-K  [C_0402]  141.1 155.34 180 top
CV30  2.2U_0402_6.3V6-K  [C_0402]  148.57 154.12 0 top
CV31  10U_0603_6.3V6-M  [C_0603]  138.08 146.85 270 top
CV32  10U_0603_6.3V6-M  [C_0603]  138.18 142.24 90 top
CV33  1U_0402_10V6-K  [C_0402]  136.02 141.09 90 top
CV34  1U_0402_10V6-K  [C_0402]  140.47 142.15 90 top
CV35  1U_0402_10V6-K  [C_0402]  160.84 140.83 0 top
CV36  1U_0402_10V6-K  [C_0402]  140.47 140.22 0 top
CV37  1U_0402_10V6-K  [C_0402]  136.91 141.09 90 top
CV38  1U_0402_10V6-K  [C_0402]  138.72 140.22 0 top
CV39  2.2U_0402_6.3V6-K  [C_0402]  142.17 148.69 270 top
CV40  2.2U_0402_6.3V6-K  [C_0402]  144.24 148.64 270 top
CV41  2.2U_0402_6.3V6-K  [C_0402]  146.17 148.62 270 top
CV42  2.2U_0402_6.3V6-K  [C_0402]  148.11 150.69 270 top
CV43  2.2U_0402_6.3V6-K  [C_0402]  142.18 150.65 270 top
CV44  2.2U_0402_6.3V6-K  [C_0402]  142.14 146.67 270 top
CV45  2.2U_0402_6.3V6-K  [C_0402]  142.15 144.67 270 top
CV46  2.2U_0402_6.3V6-K  [C_0402]  141.81 142.69 270 top
CV47  10U_0603_6.3V6-M  [C_0603]  149.88 150.53 0 top
CV48  10U_0603_6.3V6-M  [C_0603]  141.18 152.53 90 top
CV49  10U_0603_6.3V6-M  [C_0603]  170.62 143.36 270 top
CV50  10U_0603_6.3V6-M  [C_0603]  169.17 150.57 90 top
CV51  10U_0603_6.3V6-M  [C_0603]  149.78 146.8 0 top
CV52  10U_0603_6.3V6-M  [C_0603]  171.89 143.36 270 top
CV53  1U_0402_10V6-K  [C_0402]  149.54 152.03 180 top
CV54  2.2U_0402_6.3V6-K  [C_0402]  144.24 146.7 270 top
CV55  2.2U_0402_6.3V6-K  [C_0402]  146.16 146.65 270 top
CV56  2.2U_0402_6.3V6-K  [C_0402]  148.06 148.66 270 top
CV57  2.2U_0402_6.3V6-K  [C_0402]  146.16 150.63 270 top
CV58  2.2U_0402_6.3V6-K  [C_0402]  144.22 150.61 270 top
CV59  2.2U_0402_6.3V6-K  [C_0402]  144.22 144.66 270 top
CV60  2.2U_0402_6.3V6-K  [C_0402]  143.95 142.69 270 top
CV61  2.2U_0402_6.3V6-K  [C_0402]  145.85 142.86 270 top
CV62  1U_0402_10V6-K  [C_0402]  149.74 144.97 180 top
CV63  1U_0402_10V6-K  [C_0402]  148.52 152.92 180 top
CV64  10U_0603_6.3V6-M  [C_0603]  170.41 150.57 90 top
CV65  10U_0603_6.3V6-M  [C_0603]  171.68 150.57 90 top
CV66  1U_0402_10V6-K  [C_0402]  140.25 148.67 270 top
CV67  1U_0402_10V6-K  [C_0402]  140.21 146.67 270 top
CV68  1U_0402_10V6-K  [C_0402]  145.98 153.28 270 top
CV69  0.1U_0402_10V7-K  [C_0402]  145.09 153.28 270 top
CV70  0.1U_0402_10V7-K  [C_0402]  140.16 144.85 270 top
CV71  10U_0603_6.3V6-M  [C_0603]  149.07 141.7 180 top
CV72  1U_0402_10V6-K  [C_0402]  149.05 143.19 0 top
CV73  1U_0402_10V6-K  [C_0402]  127.64 130.65 270 bottom
CV74  1U_0402_10V6-K  [C_0402]  133.89 130.65 270 bottom
CV75  1U_0402_10V6-K  [C_0402]  130.28 130.65 270 bottom
CV76  1U_0402_10V6-K  [C_0402]  137.5 130.67 270 bottom
CV77  120P_0402_50V8-J  [C_0402]  166.4 155.51 0 bottom
CV78  68P_0402_50V8-J  [C_0402]  151.03 155.31 180 top
CV79  0.1U_0402_10V7-K  [C_0402]  117.17 138.54 90 bottom
CV80  0.1U_0402_10V7-K  [C_0402]  110.37 144.39 270 top
CV83  10U_0603_6.3V6-M  [C_0603]  108.2 135.72 90 top
CV84  1U_0402_10V6-K  [C_0402]  102.34 144.23 90 top
CV85  1U_0402_10V6-K  [C_0402]  111.84 136.49 0 top
CV86  1U_0402_10V6-K  [C_0402]  101.15 140.25 270 bottom
CV87  1U_0402_10V6-K  [C_0402]  106.2 144.34 270 top
CV88  1U_0402_10V6-K  [C_0402]  115.2 144.52 270 top
CV96  0.1U_0402_10V7-K  [C_0402]  103.66 142.61 90 top
CV97  0.1U_0402_10V7-K  [C_0402]  114.38 140.42 180 top
CV98  0.1U_0402_10V7-K  [C_0402]  101.09 136.35 90 bottom
CV99  0.1U_0402_10V7-K  [C_0402]  116.39 133.77 90 bottom
CV100  0.1U_0402_10V7-K  [C_0402]  105.57 136.41 180 top
CV106  0.1U_0402_10V7-K  [C_0402]  116.46 163.59 90 bottom
CV107  0.1U_0402_10V7-K  [C_0402]  111.43 167.45 0 top
CV111  10U_0603_6.3V6-M  [C_0603]  105.41 158.2 0 top
CV112  1U_0402_10V6-K  [C_0402]  104.78 166 90 top
CV113  1U_0402_10V6-K  [C_0402]  102.34 165.85 90 top
CV114  1U_0402_10V6-K  [C_0402]  115.32 155.74 90 top
CV115  1U_0402_10V6-K  [C_0402]  104.77 164.21 90 top
CV116  1U_0402_10V6-K  [C_0402]  106.93 165.69 270 top
CV117  10U_0603_6.3V6-M  [C_0603]  110.24 163.48 90 top
CV118  1U_0402_10V6-K  [C_0402]  101.09 157.97 90 bottom
CV119  1U_0402_10V6-K  [C_0402]  101.19 162.27 270 bottom
CV120  1U_0402_10V6-K  [C_0402]  110.29 154.32 90 top
CV121  1U_0402_10V6-K  [C_0402]  102.34 157.87 90 top
CV122  1U_0402_10V6-K  [C_0402]  115.19 166.2 270 top
CV123  0.1U_0402_10V7-K  [C_0402]  102.24 164.37 270 top
CV124  0.1U_0402_10V7-K  [C_0402]  115.32 153.58 90 top
CV125  0.1U_0402_10V7-K  [C_0402]  115.98 163.2 90 top
CV126  0.1U_0402_10V7-K  [C_0402]  106.28 163.08 270 top
CV127  0.1U_0402_10V7-K  [C_0402]  110.39 156.32 90 top
CV128  0.1U_0402_10V7-K  [C_0402]  101.09 153.37 90 bottom
CV129  0.1U_0402_10V7-K  [C_0402]  101.09 155.4 90 bottom
CV130  0.1U_0402_10V7-K  [C_0402]  116.32 154.3 270 bottom
CV131  0.1U_0402_10V7-K  [C_0402]  112.19 163.56 0 top
CV132  0.1U_0402_10V7-K  [C_0402]  103.86 154.27 270 top
CV133  0.1U_0402_10V7-K  [C_0402]  133.18 171.92 0 bottom
CV134  0.1U_0402_10V7-K  [C_0402]  140.47 176.77 270 top
CV137  10U_0603_6.3V6-M  [C_0603]  136.51 177.97 0 top
CV138  1U_0402_10V6-K  [C_0402]  129.34 177.81 0 top
CV139  1U_0402_10V6-K  [C_0402]  128.76 172.89 0 top
CV140  1U_0402_10V6-K  [C_0402]  137.37 185.89 180 top
CV141  1U_0402_10V6-K  [C_0402]  135.06 173.6 90 top
CV142  1U_0402_10V6-K  [C_0402]  126.6 172.89 0 top
CV150  0.1U_0402_10V7-K  [C_0402]  135.77 181.9 180 top
CV151  0.1U_0402_10V7-K  [C_0402]  135.31 187.24 180 bottom
CV152  0.1U_0402_10V7-K  [C_0402]  127.29 184.34 180 top
CV153  0.1U_0402_10V7-K  [C_0402]  124.29 180.79 90 bottom
CV154  0.1U_0402_10V7-K  [C_0402]  136.45 176.01 270 top
CV160  0.1U_0402_10V7-K  [C_0402]  155.13 171.97 0 bottom
CV161  0.1U_0402_10V7-K  [C_0402]  162.77 176.65 270 top
CV163  4.7U_0603_6.3V6-K  [C_0603]  182.11 130.85 180 bottom
CV165  10U_0603_6.3V6-M  [C_0603]  158.51 177.97 0 top
CV166  1U_0402_10V6-K  [C_0402]  150.42 171.87 0 bottom
CV167  1U_0402_10V6-K  [C_0402]  157.77 181.9 180 top
CV168  1U_0402_10V6-K  [C_0402]  160.87 185.87 0 top
CV169  1U_0402_10V6-K  [C_0402]  159.37 185.89 180 top
CV170  1U_0402_10V6-K  [C_0402]  158.58 176.01 270 top
CV177  0.1U_0402_10V7-K  [C_0402]  160.97 182.79 0 top
CV178  0.1U_0402_10V7-K  [C_0402]  160.71 181.27 180 top
CV179  0.1U_0402_10V7-K  [C_0402]  159.44 182.79 90 top
CV180  0.1U_0402_10V7-K  [C_0402]  152.89 185.87 0 top
CV181  0.1U_0402_10V7-K  [C_0402]  157.29 187.01 180 bottom
CV187  0.1U_0402_10V7-K  [C_0402]  183.24 128.56 0 top
CV205  0.1U_0402_10V7-K  [C_0402]  164.14 156.3 90 top
CV206  0.1U_0402_10V7-K  [C_0402]  168.89 153.46 0 top
CV207  0.1U_0402_10V7-K  [C_0402]  166.45 155.87 0 top
CV208  10U_0603_6.3V6-M  [C_0603]  168.65 155.49 0 top
CV209  0.1U_0402_25V6-K  [C_0402]  164.65 126.86 270 top
CV210  0.082U_0402_50V7-K  [C_0402]  148.77 138.85 180 top
CV211  0.1U_0402_10V7-K  [C_0402]  159.49 130.85 0 top
CV212  0.1U_0402_10V7-K  [C_0402]  156.27 130.55 270 bottom
CV213  0.1U_0402_10V7-K  [C_0402]  161.27 130.98 0 top
CV214  0.1U_0402_10V7-K  [C_0402]  151.24 153.38 90 top
CV215  0.1U_0402_10V7-K  [C_0402]  158.25 130.09 180 top
CV216  10U_0603_6.3V6-M  [C_0603]  158.49 128.94 180 top
CV217  1U_0402_10V6-K  [C_0402]  158.25 131.1 180 top
CV218  0.1U_0402_10V7-K  [C_0402]  137.01 155.23 270 top
CV219  1U_0402_10V6-K  [C_0402]  137.9 155.23 270 top
CV220  10U_0603_6.3V6-M  [C_0603]  139.05 155.31 270 top
CV221  1U_0402_10V6-K  [C_0402]  160.58 159.63 270 top
CV222  10U_0603_6.3V6-M  [C_0603]  162.55 159.55 0 top
CV223  1U_0402_10V6-K  [C_0402]  164.9 164.2 270 top
CV224  0.1U_0402_10V7-K  [C_0402]  165.79 164.2 270 top
CV225  0.1U_0402_10V7-K  [C_0402]  161.47 159.63 270 top
CV226  10U_0603_6.3V6-M  [C_0603]  166.93 164.44 270 top
CV227  1U_0402_10V6-K  [C_0402]  139.6 142.15 90 top
CV228  .01U_0402_16V7-K  [C_0402]  174.17 122.01 90 top
CV229  0.22U_0402_10V6-K  [C_0402]  185.86 126.71 90 top
CV232  1U_0402_6.3V6-K  [C_0402]  173.79 182.49 270 top
CV233  0.1U_0402_10V7-K  [C_0402]  165.49 183.05 180 top
CV236  0.1U_0402_10V7-K  [C_0402]  170.59 174.03 270 top
CV237  1U_0402_6.3V6-K  [C_0402]  174.02 175.15 0 top
CV238  0.1U_0402_10V7-K  [C_0402]  173.28 170.73 0 top
CV239  820P_0402_50V7-K  [C_0402]  171.89 170.73 180 top
CV240  0.22U_0402_10V6-K  [C_0402]  173.03 176.57 90 top
CV241  0.1U_0402_10V7-K  [C_0402]  164.76 179.17 0 top
CVG15  0.1U_0402_10V6-K  [C_0402]  34.78 89.22 180 top
CVG16  0.1U_0402_10V6-K  [C_0402]  34.78 88.34 180 top
CVG17  0.1U_0402_10V6-K  [C_0402]  34.78 92.02 180 top
CVG18  0.1U_0402_10V6-K  [C_0402]  34.78 91.13 180 top
CVG19  0.1U_0402_10V6-K  [C_0402]  34.78 87.32 180 top
CVG20  0.1U_0402_10V6-K  [C_0402]  34.78 86.43 180 top
CVG32  12P_0402_50V8-J  [C_0402]  24.77 83.3 180 top
CVG33  12P_0402_50V8-J  [C_0402]  25.89 83.22 0 top
CVG34  0.1U_0402_10V6-K  [C_0402]  31.04 93.51 90 top
CVG35  0.1U_0402_10V6-K  [C_0402]  29.77 83.73 270 top
CVG36  0.1U_0402_10V6-K  [C_0402]  34.73 85 270 top
CVG37  0.1U_0402_10V6-K  [C_0402]  23.68 91.23 180 top
CVG38  0.1U_0402_10V6-K  [C_0402]  33.71 85 270 top
CVG39  0.1U_0402_10V6-K  [C_0402]  27.87 82.97 0 top
CVG40  0.1U_0402_10V6-K  [C_0402]  27.87 83.86 0 top
CVG41  0.1U_0402_10V6-K  [C_0402]  33.84 90.21 0 top
CVG42  2.2U_0603_6.3V6-K  [C_0603]  36.15 84.94 270 top
CVG43  1U_0402_10V6K  [C_0402]  30.16 94.4 270 top
CVG44  4.7U_0402_6.3V6-M  [C_0402]  29.77 80.68 90 top
CW1  4.7U_0603_6.3V6-K  [C_0603]  41.84 30.41 270 top
CW2  0.1U_0402_10V7-K  [C_0402]  45.85 29.96 270 top
CW3  1U_0402_10V6-K  [C_0402]  49.59 26.89 270 top
CW4  0.1U_0402_10V7-K  [C_0402]  43.16 32.76 90 top
CW5  10U_0603_6.3V6-M  [C_0603]  44.88 31.66 180 top
CW6  0.1U_0402_10V7-K  [C_0402]  45.83 31.84 270 top
CW7  0.1U_0402_10V7-K  [C_0402]  54.11 28.92 0 top
CW8  4.7U_0603_6.3V6-K  [C_0603]  54.17 27.85 0 top
CW9  0.1U_0402_10V7-K  [C_0402]  49.33 36.03 270 top
CW10  0.1U_0402_10V7-K  [C_0402]  48.44 36.03 270 top
CW11  5P_0402_50V9-C  [C_0402]  49.54 26.71 180 bottom
CW12  0.1U_0402_10V7-K  [C_0402]  31.38 33.57 180 bottom
CW13  10U_0603_6.3V6-M  [C_0603]  31.62 34.71 180 bottom
CW14  10P_0402_50V8-J  [C_0402]  29.14 33.62 90 bottom
CX2  2.2U_0402_6.3V6-K  [C_0402]  30.56 69.56 270 top
CX3  0.1U_0402_10V7-K  [C_0402]  27 69.55 270 top
CX4  0.1U_0402_10V7-K  [C_0402]  27.89 69.55 270 top
CX5  0.1U_0402_10V7-K  [C_0402]  25.22 69.55 270 top
CX6  0.1U_0402_10V7-K  [C_0402]  26.11 69.55 270 top
CX7  0.1U_0402_10V7-K  [C_0402]  22.51 69.55 270 top
CX8  0.1U_0402_10V7-K  [C_0402]  23.4 69.55 270 top
CX9  0.1U_0402_10V7-K  [C_0402]  20.73 69.55 270 top
CX10  0.1U_0402_10V7-K  [C_0402]  21.62 69.55 270 top
CX11  0.1U_0402_10V7-K  [C_0402]  30.05 66.71 0 top
CX12  .01U_0402_16V7-K  [C_0402]  18.29 58.33 180 top
CX13  0.1U_0402_10V7-K  [C_0402]  19.79 68.8 180 top
CX14  .01U_0402_16V7-K  [C_0402]  27.36 57.27 270 top
CX15  0.1U_0402_10V7-K  [C_0402]  30.96 63.91 180 top
CX16  0.1U_0402_10V7-K  [C_0402]  30.96 63.02 180 top
D1  -  [PESD5V0U2BT_SOT23-3]  94.9 128.59 225 bottom
D4  -  [AZC199-02SPR7G_SOT23-3]  205.07 99.35 270 top
D5  -  [RB491D_SOT23-3]  17.46 98.95 180 bottom
D6  -  [RB751V-40_SOD323-2]  233.46 153.71 90 bottom
D7  -  [CM1293A-04SO_SC-74-6]  16.71 46.85 0 top
D8  -  [RCLAMP0524PATCT_SLP2510P8-10-9]  17.78 43.84 270 top
D11  -  [RB521CS-30GT2RA_VMN2-2]  234.89 146.29 0 top
D12  -  [RCLAMP0524PATCT_SLP2510P8-10-9]  14.72 66.32 270 bottom
D13  -  [RCLAMP0524PATCT_SLP2510P8-10-9]  13.77 62.46 270 top
D14  -  [RCLAMP0524PATCT_SLP2510P8-10-9]  13.77 66.37 270 top
D15  RB521CM_30  [RB521CS-30GT2RA_VMN2-2]  128.33 68.79 270 top
D16  -  [RCLAMP0524PATCT_SLP2510P8-10-9]  19.79 16.61 270 top
D17  -  [CM1293A-04SO_SC-74-6]  18.97 18.12 0 top
D59  RB521CM_30  [RB521CS-30GT2RA_VMN2-2]  208.65 55.44 90 top
D60  -  [RB521CS-30GT2RA_VMN2-2]  234.89 147.28 0 top
D61  RB521CM_30  [RB521CS-30GT2RA_VMN2-2]  212.02 62.87 270 top
D62  RB521CM_30  [RB521CS-30GT2RA_VMN2-2]  190.49 40.52 270 top
D63  RB521CM_30  [RB521CS-30GT2RA_VMN2-2]  199.76 39.76 270 top
D64  RB521CM_30  [RB521CS-30GT2RA_VMN2-2]  185.29 35.32 90 top
D65  RB521CM_30  [RB521CS-30GT2RA_VMN2-2]  208.62 54.21 0 top
DA1  -  [BAT54CW_SOT323-3]  197.32 29.76 270 top
DA5  -  [RB751V-40_SOD323-2]  217.25 25.54 270 top
DA6  -  [RB751V-40_SOD323-2]  216.87 14.34 90 top
DA7  -  [RB751V-40_SOD323-2]  218.57 14.34 90 top
DC23  -  [RB521CS-30GT2RA_VMN2-2]  69.4 110.25 270 bottom
DEV1  -  [RB751V-40_SOD323-2]  193.5 35.35 90 top
DL1  -  [RCLAMP0524PATCT_SLP2510P8-10-9]  41.26 120.42 270 bottom
DL2  -  [RCLAMP0524PATCT_SLP2510P8-10-9]  40.93 115.62 270 bottom
DL3  -  [LSE-200NX3216TRLF_1206-2]  21.85 126.2 0 bottom
DL4  -  [LSE-200NX3216TRLF_1206-2]  21.09 122.09 0 bottom
DL5  -  [LSE-200NX3216TRLF_1206-2]  21.44 112.46 0 bottom
DL6  -  [LSE-200NX3216TRLF_1206-2]  21.44 110.05 0 bottom
DT1  -  [CM1293A-04SO_SC-74-6]  9.91 85.19 270 top
DT2  -  [CM1293A-04SO_SC-74-6]  13.19 89.87 90 top
DV4  -  [RB751V-40_SOD323-2]  163.24 128.5 180 bottom
DV5  -  [RB751V-40_SOD323-2]  163.99 151.45 270 top
DV7  -  [RB751V-40_SOD323-2]  176.21 176.57 180 top
F2  0.5A_8V_KMC3S050RY  [F_KMC3S050RY]  18.32 95.29 180 bottom
FD1  CF  [FIDUCIAL_C40M80]  209.61 4.18 180 bottom
FD2  CF  [FIDUCIAL_C40M80]  105.85 181.52 180 bottom
FD3  CF  [FIDUCIAL_C40M80]  105.85 181.52 0 top
FD4  CF  [FIDUCIAL_C40M80]  20.88 8.17 0 top
FD5  CF  [FIDUCIAL_C40M80]  12.6 2.76 180 bottom
FD6  CF  [FIDUCIAL_C40M80]  209.61 4.18 0 top
H1  -  [PAD_C6P0D3P15]  59.37 104.65 0 top
H2  -  [PAD_C6P0D3P15]  119.37 104.65 0 top
H3  -  [PAD_C6P0D3P15]  59.37 82.65 0 top
H4  -  [PAD_C6P0D3P15]  119.37 82.65 0 top
H5  -  [PAD_C6P0D3P15]  120.35 159.26 0 top
H6  -  [PAD_C6P0D3P15]  167.65 136.26 0 top
H8  -  [PAD_C6P0D2P3]  217.5 186 0 top
H9  -  [PAD_C6P0D2P3]  214 162.5 0 top
H10  -  [PAD_C6P0D2P3]  227.2 100.7 0 top
H11  -  [PAD_C6P0D2P3]  222 55.5 0 top
H12  -  [PAD_C6P0D2P3]  224 31.5 0 top
H13  -  [PAD_C6P0D2P3]  54.5 6 0 top
H14  -  [PAD_C6P0D2P3]  141 6 0 top
H15  -  [PAD_C6P0D2P3]  23.56 37 0 top
H16  -  [PAD_C6P0D2P3]  7.5 6 0 top
H17  -  [PAD_C6P0D2P3]  82 122.5 0 top
H18  -  [PAD_C6P0D2P3]  216 6 0 top
H19  PAD_shapeT6P0X8P5CB6P0D2P3  [PAD_SHAPET6P0X8P5CB6P0D2P3]  23.55 100 0 top
H20  -  [PAD_C6P0D2P3]  98 183 0 top
H21  -  [PAD_C2P3D2P3N]  179 188 0 top
H22  PAD_shapeT6P0X8P5CB6P0D2P3  [PAD_SHAPET6P0X8P5CB6P0D2P3]  152 125.5 0 top
H23  -  [PAD_C6P0D2P3]  142 66.5 0 top
H24  -  [PAD_C6P0D2P3]  142.5 33.5 0 top
H25  -  [PAD_C6P0D2P3]  14 73.5 0 top
H26  -  [PAD_O2P3X2P8D2P3X2P8N]  13.5 7.5 90 top
H27  PAD_shapeT6P0X8P5CB6P0D2P3  [PAD_SHAPET6P0X8P5CB6P0D2P3]  222.96 139.67 0 top
H28  -  [PAD_C3P5D2P3]  14.65 107.75 0 top
IT1  Test_Point_40MIL  [TPC40]  195.48 36.31 0 top
IT2  Test_Point_40MIL  [TPC40]  193.58 38.9 0 top
IT3  Test_Point_40MIL  [TPC40]  180.88 56.43 0 top
IT4  Test_Point_40MIL  [TPC40]  210.24 49.57 0 top
IT5  Test_Point_40MIL  [TPC40]  200.82 36.77 0 top
IT6  Test_Point_40MIL  [TPC40]  183.06 58.74 0 top
IT7  Test_Point_40MIL  [TPC40]  176.46 54.84 0 top
IT8  Test_Point_40MIL  [TPC40]  208.59 49.19 0 top
J1  SHORT PADS  [SHORTPADS]  223.09 122.26 180 bottom
J5  -  [JUMP_43X118]  188.27 27.89 90 top
J6  -  [JUMP_43X118]  187.31 21.62 270 top
JAUF  ACES_50506-01201-001  [ACES_50506-01201-001_12P-T]  220.7 5.65 270 top
JBATT1  SUYIN_200082GR007M211ZR  [SUYIN_200082GR007M211ZR_7P-T]  192.66 187.85 0 bottom
JC1  -  [JUMP_43X79]  86.57 70.55 90 top
JC5  -  [JUMP_43X118]  133.05 73.61 90 bottom
JCMOS1  SHORT PADS  [SHORTPADS]  126.99 69.7 0 bottom
JCP  ACES_50506-01201-AT1  [ACES_50506-01201-AT1_12P]  34.55 95.2 270 top
JCRT  SUYIN_070546HR015S21BZR  [SUYIN_070546HR015S21BZR_15P-T]  6.1 86.42 270 bottom
JDCIN1  ACES_50271-00701-001  [ACES_50271-00701-001_7P-T]  234.24 174.66 0 bottom
JDIMM1  LCN_DAN06-K4406-0102  [LCN_DAN06-K4406-0102_204P]  59.92 37.15 0 bottom
JDIMM2  LCN_DAN06-K4406-0103  [LCN_DAN06-K4406-0103_204P]  59.92 50.35 180 bottom
JFAN  ACES_85205-05001  [ACES_85205-05001_5P-T]  56.5 116.9 0 bottom
JFPB  ACES_88514-0060N-071  [ACES_88514-0060N-071_6P-T]  212.45 92.65 90 top
JHDD  ACES_50812-0227P-001  [ACES_50812-0227P-001_22P-T]  171.42 125.43 180 bottom
JHDMI  CONCR_099ATAC19NBLCNF  [CONCR_099ATAC19NBLCNF_19P]  9.45 57.51 90 bottom
JKB  JAE_FL10F032HA2R3000  [JAE_FL10F032HA2R3000_32P]  160.39 117.85 0 top
JLCD  I-PEX_20474-040E-12  [I-PEX_20474-040E-12_40P-T]  99.07 140.2 45 top
JME1  SHORT PADS  [SHORTPADS]  126.99 71.03 0 bottom
JODD  ACES_50885-0137P-001  [ACES_50885-0137P-001_13P-T]  228.8 40.66 270 bottom
JREAD2  SUYIN_250312HB011M106ZL  [SUYIN_250312HB011M106ZL_11P]  37.78 30.85 180 bottom
JRJ452  FOX_JM3611-RS800013-7H  [FOX_JM3611-RS800013-7H_12P-T]  14.48 114.93 270 bottom
JRTC  TE_2041180-2  [TE_2041180-2_2P-T]  231.19 152.74 315 bottom
JSPK  TYCO_2041180-4  [TYCO_2041180-4_4P-T]  234.38 187.2 0 bottom
JTOUCH  ACES_50463-0104A-P01  [ACES_50463-0104A-P01_10P-T]  237.63 146.7 270 top
JTP  JAE_FL10F012HA1R3000  [JAE_FL10F012HA1R3000_12P]  183.17 121.25 180 top
JU3LC  ACES_50406-02071-001  [ACES_50406-02071-001_20P]  232.61 144.26 45 bottom
JU3LF  HIGHS_FC5AF261-1151H  [HIGHS_FC5AF261-1151H_26P-T]  244.27 167.55 270 top
JUSB1  TAITW_PUBAU1-09FNLSCNN4H0  [TAITW_PUBAU1-09FNLSCNN4H0_9P-T]  14.21 45.5 270 bottom
JUSB2  TAITW_PUBAU1-09FNLSCNN4H0  [TAITW_PUBAU1-09FNLSCNN4H0_9P-T]  14.21 22.9 270 bottom
JV1  -  [JUMP_43X118]  180.65 128.44 180 top
JV4  -  [JUMP_43X39]  166.35 123.03 180 top
JWLBT  TYCO_2199230-8  [TYCO_2199230-8_75P-T]  241.86 183.4 270 bottom
L1  EXC24CH900U_4P  [PANAS_EXC24CH900U_4P]  17.99 64.15 90 top
L2  EXC24CH900U_4P  [PANAS_EXC24CH900U_4P]  17.91 62.27 90 top
L3  EXC24CH900U_4P  [PANAS_EXC24CH900U_4P]  17.96 60.29 90 top
L4  EXC24CH900U_4P  [PANAS_EXC24CH900U_4P]  18.04 66.31 90 top
L5  EXC24CH900U_4P  [PANAS_EXC24CH900U_4P]  238.97 174.89 0 top
L6  EXC24CH900U_4P  [PANAS_EXC24CH900U_4P]  231.6 142.99 0 top
L7  EXC24CH900U_4P  [PANAS_EXC24CH900U_4P]  238.79 155.41 315 bottom
L8  EXC24CH900U_4P  [PANAS_EXC24CH900U_4P]  233.58 159.48 270 top
L9  EXC24CH900U_4P  [PANAS_EXC24CH900U_4P]  21.72 43.4 90 top
L10  EXC24CH900U_4P  [PANAS_EXC24CH900U_4P]  21.67 41.75 90 top
L11  EXC24CH900U_4P  [PANAS_EXC24CH900U_4P]  21.49 47.87 90 top
L12  EXC24CH900U_4P  [PANAS_EXC24CH900U_4P]  228.73 143.5 0 top
L13  EXC24CH900U_4P  [PANAS_EXC24CH900U_4P]  239.22 180.43 270 top
L15  EXC24CH900U_4P  [PANAS_EXC24CH900U_4P]  97.57 129.08 45 top
L16  EXC24CH900U_4P  [PANAS_EXC24CH900U_4P]  89.3 123.48 315 top
L17  EXC24CH900U_4P  [PANAS_EXC24CH900U_4P]  87.87 124.67 315 top
L18  EXC24CH900U_4P  [PANAS_EXC24CH900U_4P]  24.14 14.26 90 top
L19  EXC24CH900U_4P  [PANAS_EXC24CH900U_4P]  24.03 16.25 90 top
L20  EXC24CH900U_4P  [PANAS_EXC24CH900U_4P]  24.75 19.14 90 top
L21  4.7UH_TLPC4012C-4R7M_1.25A_20%  [TAI-T_TLPC4012C-4R7M_2P]  32.95 81.79 270 bottom
L22  EXC24CH900U_4P  [PANAS_EXC24CH900U_4P]  236.3 141.62 270 top
LC1  0_0805_5%  [R0805_SHORT]  124.11 97 0 bottom
LC2  0_0805_5%  [R0805_SHORT]  122.7 96.43 180 bottom
LC3  0_0805_5%  [R0805_SHORT]  110.1 115.77 90 top
LC4  0_0805_5%  [R0805_SHORT]  106.23 115.77 90 top
LC5  0_0805_5%  [R0805_SHORT]  107.94 115.77 90 top
LE1  BLM18PG121SN1D_2P  [MURAT_BLM18PG121SN1D_2P]  179.96 54.1 0 top
LE2  BLM18PG121SN1D_2P  [MURAT_BLM18PG121SN1D_2P]  181.16 52.57 180 top
LL1  4.7UH_ LQH32PN4R7NN0L_30%  [TDK_FLF3215T-4R7M_2P]  48.39 123.97 90 bottom
LT1  BLM15BB220SN1D_2P  [MURAT_BLM15BB220SN1D_2P]  14.53 83.99 90 top
LT2  BLM15BB220SN1D_2P  [MURAT_BLM15BB220SN1D_2P]  14.53 81.71 90 top
LT3  BLM15BB220SN1D_2P  [MURAT_BLM15BB220SN1D_2P]  14.53 79.42 90 top
LV3  BLM18PG221SN1D_2P  [MURAT_BLM18PG221SN1D_2P]  126.4 129.63 90 bottom
LV4  BLM18PG121SN1D_2P  [MURAT_BLM18PG121SN1D_2P]  163.85 160.82 180 top
LV5  BLM18PG121SN1D_2P  [MURAT_BLM18PG121SN1D_2P]  168.2 163.19 90 top
LV6  BLM15PX121SN1D_2P  [MURAT_BLM15PX121SN1D_2P]  157.42 127.67 0 top
NOREF  -  []  73.34 20.11 0 top
NOREF#2  -  []  42.6 11.7 0 top
NOREF#3  -  []  106.46 -30.06 0 top
NOREF#4  -  []  121.61 16.58 0 top
NOREF#5  -  []  79.18 17.57 0 top
NOREF#6  -  []  59.08 3.98 0 top
